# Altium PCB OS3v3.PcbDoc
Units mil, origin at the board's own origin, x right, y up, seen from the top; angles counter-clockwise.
Board outline 889.29 x 688.98 mil, 4 copper layers (Top Layer, MidLayer1, MidLayer2, Bottom Layer), stack 46.6 mil thick; 45 components, 34 nets, 157 pads, 70 vias.
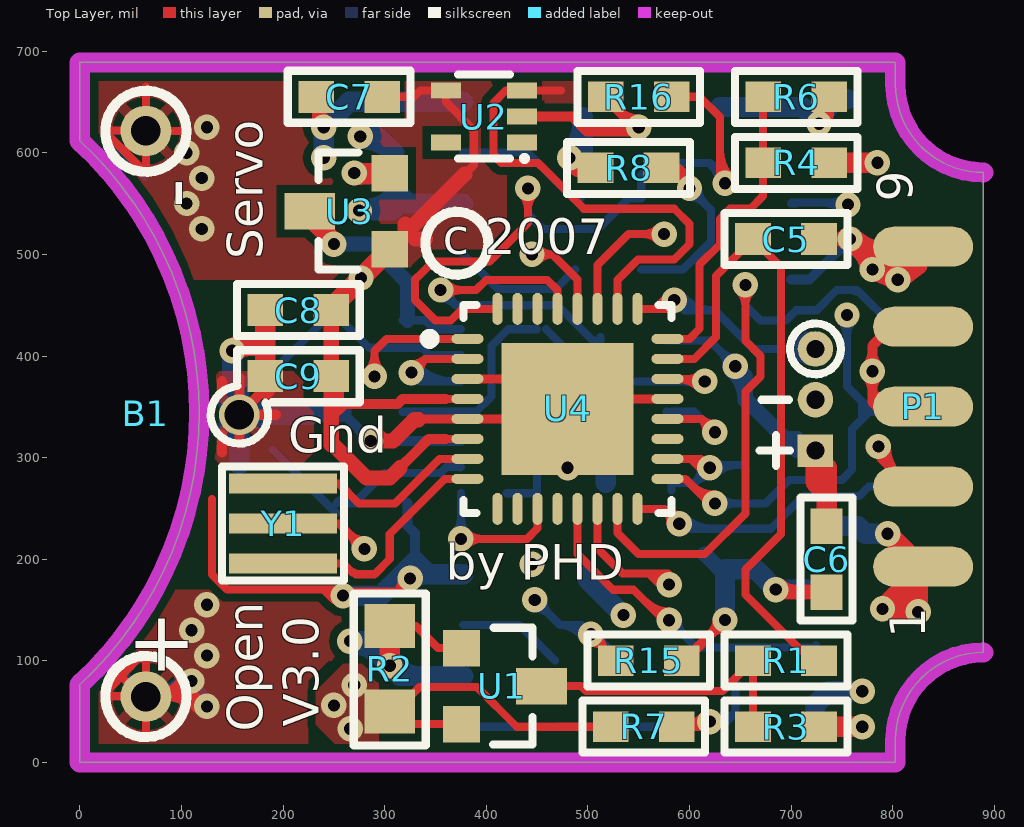
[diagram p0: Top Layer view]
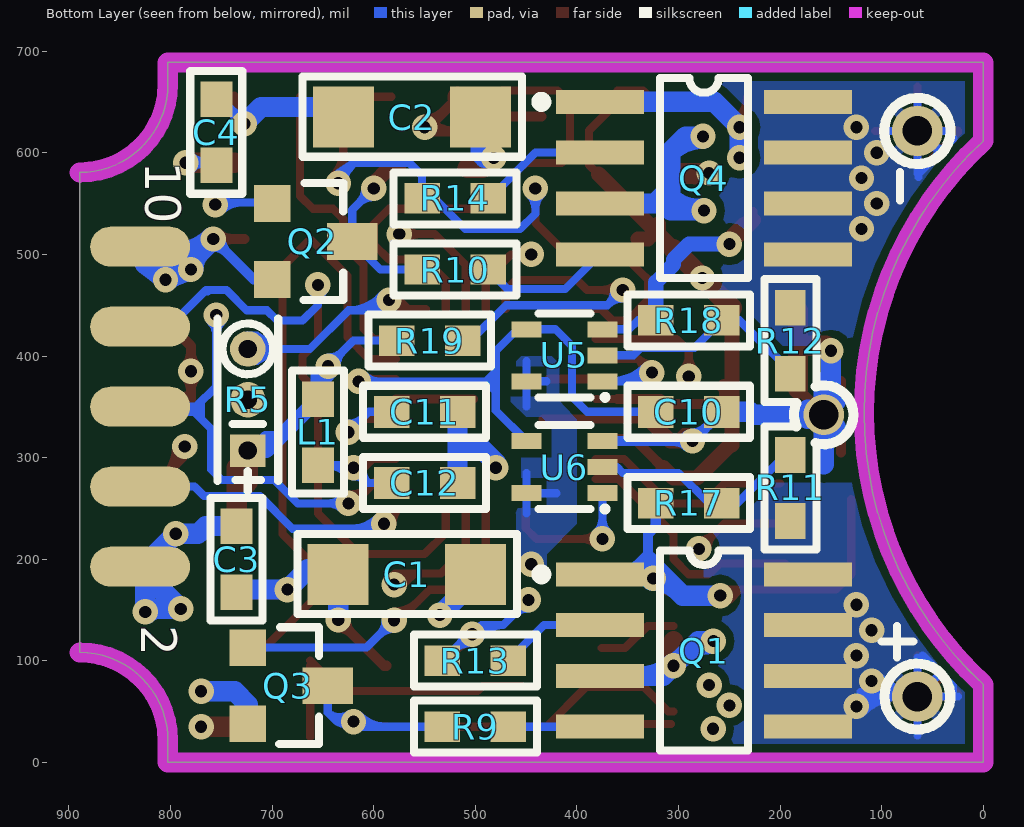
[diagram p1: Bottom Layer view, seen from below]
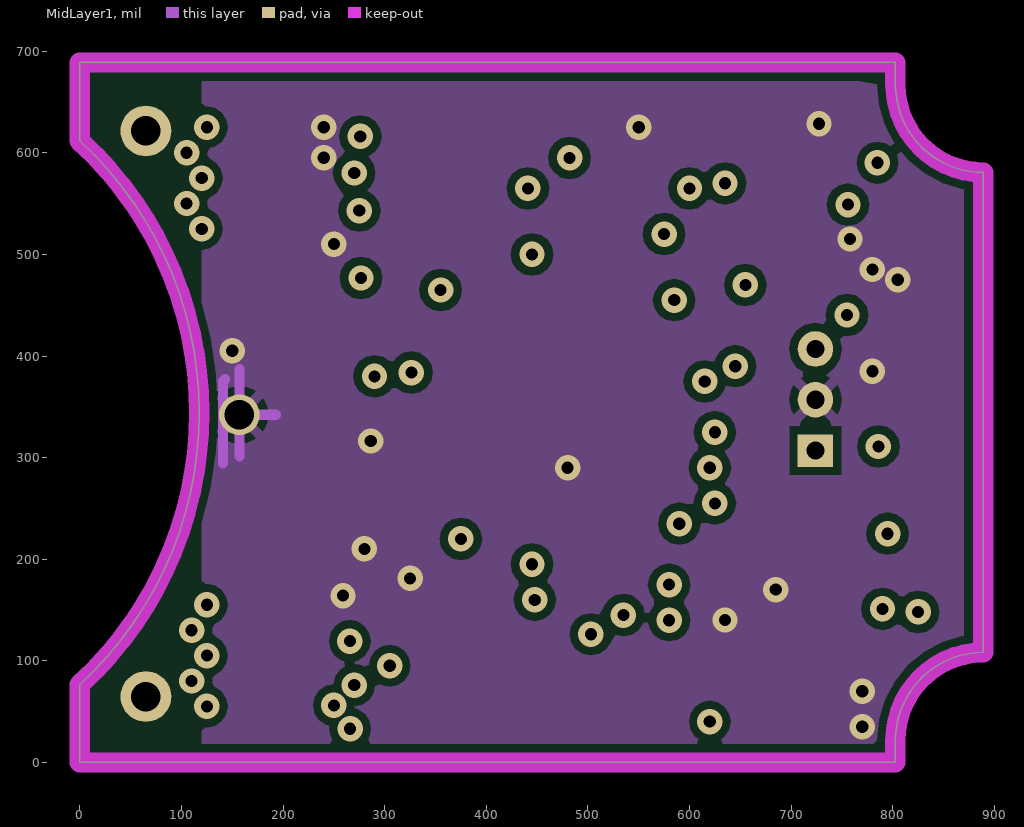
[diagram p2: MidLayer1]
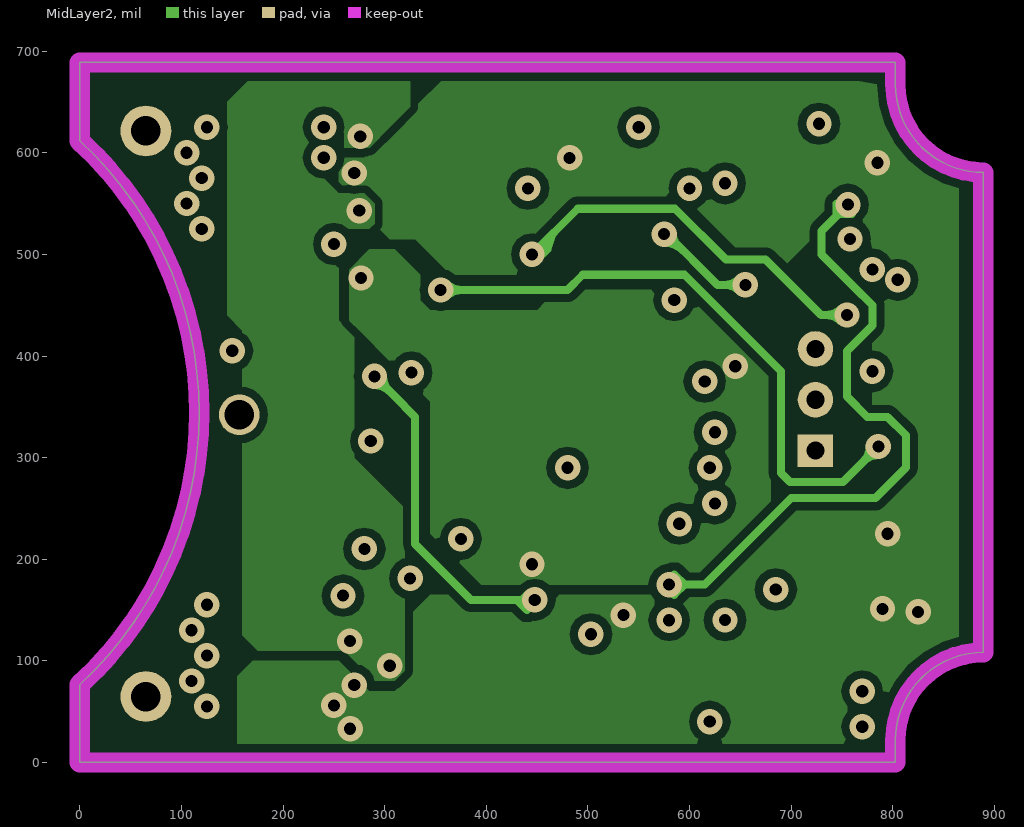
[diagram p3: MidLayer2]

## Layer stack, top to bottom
Top Layer: signal copper 1.4
Dielectric: core 5, FR-4, Dk 4.8
MidLayer1: signal copper 1.4
Dielectric: prepreg 31, FR-4, Dk 4.8
MidLayer2: signal copper 1.4
Dielectric: core 5, FR-4, Dk 4.8
Bottom Layer: signal copper 1.4

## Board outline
0,0 0,76.69 ccw(c-245.79,344.19) 117.48,344.19 ccw(c-245.79,344.19) 0,611.69 0,688.98 802.67,688.98 802.67,667.32 ccw(c889.29,667.32) 889.29,580.71 889.29,108.27 ccw(c889.29,21.65) 802.67,21.65 802.67,0

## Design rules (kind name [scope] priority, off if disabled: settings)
Clearance [All] p1: gap=8
ComponentClearance [All] p1: gap=5 collisioncheckmode=2 verticalgap=10
PasteMaskExpansion PasteMaskExpansion_1 [HasPad('U4-33')] p1: expansion=-15
PasteMaskExpansion [All] p2: expansion=0
PlaneClearance [All] p1: clearance=16
PolygonConnect PolygonConnect_2 [OnBottomLayer or OnTopLayer] p1: connectstyle=Direct reliefconductorwidth=10 reliefentries=4 polygonreliefangle="90 Angle"
PolygonConnect PolygonConnect_1 [ISVIA] p2: connectstyle=Direct reliefconductorwidth=10 reliefentries=4 polygonreliefangle="90 Angle"
PolygonConnect [All] p3: connectstyle=Relief reliefconductorwidth=10 reliefentries=4 polygonreliefangle="45 Angle"
RoomDefinition OS3v3 [InComponentClass('OS3v3')] p1: confinementstyle=ConfineIn formatcopy=TRUE lockcomponents=FALSE outline 15,0.16 1220,0.16 1220,690.16 15,690.16
RoutingVias [All] p1: holewidth=8 width=25 viastyle="Through Hole" minholewidth=8 minwidth=25 maxholewidth=28 maxwidth=50
SolderMaskExpansion SolderMaskExpansion_1 [isvia] p1: expansion=-12.99
SolderMaskExpansion [All] p2: expansion=3
TestPointUsage [All] p1 off: valid=0 allowmultiple=FALSE
Testpoint [All] p1: side=15 testpointundercomponent=TRUE minsize=40 maxsize=100 preferedsize=60 minholesize=0 maxholesize=40 preferedholesize=32 testpointgrid=1 style=1023 order=0123456789
Width [All] p1: maxlimit=100 minlimit=8 preferedwidth=10 minimp=50.000000 maximp=50.000000 favimp=50.000000
16 further rules are at their usual default settings.

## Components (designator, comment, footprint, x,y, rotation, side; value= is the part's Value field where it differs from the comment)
B1 "Motor Servo" "SERVO PADS" 65,345.16 r90 top
C1 "10uF" C1206 500,185 r0 bottom
C2 "10uF" C1206 495,635.16 r0 bottom
C3 "1uF" C0603 735,200 r270 bottom
C4 "0.1uF" C0603 755,620.16 r90 bottom
C5 "0.1uF" C0603 695,515.16 r0 top
C6 "0.1uF" C0603 735,200.16 r270 top
C7 "0.1uF" C0603 265,655.16 r180 top
C8 "0.1uF" C0603 215,445.16 r180 top
C9 "0.1uF" C0603 215,380.16 r180 top
C10 "0.001uF" C0603 290,345.16 r0 bottom
C11 "0.1uF" C0603 550,345.16 r180 bottom
C12 "0.1uF" C0603 550,275.16 r180 bottom
L1 "INDUCTOR" C0603 655,325.16 r90 bottom
P1 "Header 5X2" FD11-10E 830,350.16 r0 top
Q1 "IRF7307" SO8 275,110.16 r270 bottom
Q2 "2N7002" SOT23-3 700,550.16 r270 bottom
Q3 "2N7002" SOT23-3 724,113 r270 bottom
Q4 "IRF7307" SO8 275,575.16 r270 bottom
R1 "1K" R0603 695,100.16 r180 top
R2 "0.05" R0805 305,50.16 r90 top
R3 "4.99K" R0603 695,35.16 r0 top
R4 "10.0K" R0603 705,590.16 r180 top
R5 "RPot" "Pot Pads" 724,357 r90 bottom
R6 "20.0K" R0603 705,655.16 r0 top
R7 "2K" R0603 555,35.16 r0 top
R8 "2K" R0603 540,585.16 r0 top
R9 "10" R0603 500,35.16 r0 bottom
R10 "10" R0603 520,485.16 r0 bottom
R11 "10.0K" R0603 190,270.16 r90 bottom
R12 "10.0K" R0603 190,415.16 r270 bottom
R13 "10" R0603 500,100.16 r0 bottom
R14 "10" R0603 520,555.16 r180 bottom
R15 "100K" R0603 560,100.16 r0 top
R16 "100K" R0603 550,655.16 r180 top
R17 "20.0K" R0603 290,255.16 r0 bottom
R18 "20.0K" R0603 290,435.16 r0 bottom
R19 "10K" R0603 545,415.16 r180 bottom
U1 "ZXCT1009" SOT23-3F 415,75.16 r270 top
U2 "MCP9701A" "SC70 -5" 435,610.16 r90 top
U3 "LM3480IM3-5.0" SOT23-3 305,505.16 r90 top
U4 "ATmega168" 32M1-A_N 480,348 r0 top
U5 "SN74CBT1G125" "SC70 -5" 375,375.16 r90 bottom
U6 "SN74CBT1G125" "SC70 -5" 375,265.16 r90 bottom
Y1 "20  MHz" MXC7T 200,235.16 r270 top

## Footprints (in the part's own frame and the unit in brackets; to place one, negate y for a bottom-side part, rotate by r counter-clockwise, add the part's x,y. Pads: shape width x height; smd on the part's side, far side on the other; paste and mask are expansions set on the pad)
32M1-A_N [mm] "QFN, 32-Leads, Body 5x5mm, Pitch 0.5mm, IPC Medium Density"
  oval 0.8x0.25 smd: 1(-2.5,1.75) 2(-2.5,1.25) 3(-2.5,0.75) 4(-2.5,0.25) 5(-2.5,-0.25) 6(-2.5,-0.75) 7(-2.5,-1.25) 8(-2.5,-1.75) 17(2.5,-1.75) 18(2.5,-1.25) 19(2.5,-0.75) 20(2.5,-0.25) 21(2.5,0.25) 22(2.5,0.75) 23(2.5,1.25) 24(2.5,1.75)
  oval 0.25x0.8 smd: 9(-1.75,-2.5) 10(-1.25,-2.5) 11(-0.75,-2.5) 12(-0.25,-2.5) 13(0.25,-2.5) 14(0.75,-2.5) 15(1.25,-2.5) 16(1.75,-2.5) 25(1.75,2.5) 26(1.25,2.5) 27(0.75,2.5) 28(0.25,2.5) 29(-0.25,2.5) 30(-0.75,2.5) 31(-1.25,2.5) 32(-1.75,2.5)
  rect 3.3x3.3 smd: 33(0,0)
  silkscreen extent -3.57,-2.6 2.6,2.6, body extent -2.58,-2.58 2.58,2.58, height 1
C0603 [mm]
  rect 0.89x0.8 smd: 1(-0.825,0) 2(0.825,0)
  silkscreen extent -1.54,-0.65 1.54,0.65
C1206 [mil]
  rect 60x60 smd: 1(0,0) 2(135,0)
  silkscreen extent -41,-40 175,39
FD11-10E [mm] "Hirose 2mm, 10 pin, TH, Edge Application"
  oval 2.5x1 smd paste-5.08: 1(0,-4) 3(0,-2) 5(0,0) 7(0,2) 9(0,4)
  oval 2.5x1 smd far side paste-5.08: 2(0,-4) 4(0,-2) 6(0,0) 8(0,2) 10(0,4)
MXC7T [mm] "TDK Ceramic Resonator"
  rect 0.5x2.7 smd: 1(-1,0) 2(0,0) 3(1,0)
  silkscreen extent -1.43,-1.53 1.43,1.53
"Pot Pads" [mil]
  rect 32x35 hole 18 paste-200: 1(-50,0)
  round 35 hole 18 paste-200: 2(0,0) 3(50,0)
  silkscreen extent -80,-30 80,30
R0603 [mm]
  rect 0.89x0.76 smd: 1(-0.825,0) 2(0.825,0)
  silkscreen extent -1.54,-0.65 1.54,0.65
R0805 [mm]
  rect 1.1x1.27 smd: 1(0,0) 2(2.14,0)
  silkscreen extent -0.85,-0.9 2.95,0.9
"SC70 -5" [mm]
  rect 0.4x0.75 smd: 1(0,0) 2(0.65,0) 3(1.3,0) 4(1.3,1.9) 5(0,1.9)
  silkscreen extent -0.41,-0.08 1.7,1.6
"SERVO PADS" [mil]
  round 50 hole 29 paste-200: 1(-280.32,0) 2(276.38,0)
  silkscreen extent -320,-40 316,40
SO8 [mm] "Small Outline; 8 Leads; Body Width 3.9 mm; Pitch 1.27 mm"
  rect 0.6x2.2 smd: 1(-1.905,-2.6) 2(-0.635,-2.6) 3(0.635,-2.6) 4(1.905,-2.6) 5(1.905,2.6) 6(0.635,2.6) 7(-0.635,2.6) 8(-1.905,2.6)
  silkscreen extent -2.5,-4.19 2.5,1.1
SOT23-3 [mil]
  rect 35.98x35.98 smd: 1(0,0)
  rect 36x36 smd: 2(74.8,0)
  rect 36x50 smd: 3(37.4,78.74)
  silkscreen extent -20,31 95,70
SOT23-3F [mm] "Zetex cw pin numbers"
  rect 0.914x1.27 smd: 1(0,1)
  rect 0.914x0.914 smd: 2(0.95,-1) 3(-0.95,-1)
  silkscreen extent -1.46,-0.21 1.46,0.78

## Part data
B1: "Servo Motor"
C1 C2 C3 C4 C5 C6 C7 C8 C9 C10 C11 C12: library part "CAP NP"
P1: "Header, 5-Pin, Dual row"
Q2 Q3: "N FET"
R1 R7 R8 R9 R10 R13 R14 R15 R16 R19: library part R
R2 R3 R4 R6 R11 R12 R17 R18: library part R, "1%"
R5: "Potentiometer"
Y1: library part CRYSTAL_0

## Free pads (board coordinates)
  round 40 hole 29 paste-200: 0(157,342.16)

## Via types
v1: diameter 25, hole 12, Top Layer to Bottom Layer, 69 vias
v2: diameter 25, hole 12, Top Layer to Bottom Layer, tented top, 1 vias

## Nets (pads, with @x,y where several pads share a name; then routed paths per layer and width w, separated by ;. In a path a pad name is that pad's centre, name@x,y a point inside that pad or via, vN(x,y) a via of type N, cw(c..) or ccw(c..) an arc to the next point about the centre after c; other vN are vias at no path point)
BATTV: R4.2 R6.1 U4.24 | length 301.6
  Top Layer w8: U4.24 600,416.9 610,426.9 610,490 630,510 630,535 640,545 660,545 672.52,557.52 R6.1
BEMFV: C10.2 U4.22 U5.4 U6.4 | length 604.3
  Top Layer w8: U4.22 602.47,377.53 ; U4.22@588.38,377.53 cw(c588.38,348.38) v1@608.99,368.99 ; 600.58,377.53 ccw(c600.58,389.42) v1@608.99,381.01 ; v1@606.57,373.92 ccw(c602.47,373.4) 602.47,377.53 ; v1@608.4,380.35 cw(c602.47,385.15) 602.47,377.53 ; v1(615,375) 605,375 602.47,377.53
  Bottom Layer w8: C10.2@317.48,345.16 390.16,345.16 405,360 405,410 421.34,426.34 U5.4 ; U6.4 480,346.54 480,405 U5.4@458.66,426.34 ; 480,365.16 489.84,375 ; 480,375 489.84,375 ; 480,384.84 489.84,375 ; v1@608.99,368.99 ccw(c594.48,354.48) 594.48,375 ccw(c594.48,395.52) v1@608.99,381.01 ; v1(615,375) 489.84,375
CURRENT: C5.1 R1.1 U4.23 | length 643.5
  Top Layer w8: U4.23 604.66,397.21 626,418.55 626,478.64 C5.1 690,487.68 690,225 655,190 655,165 719.84,100.16 R1.1
EN_A: R14.1 R16.1 U4.32 | length 792
  Top Layer w8: U4.32 376.43,446.43 365,435 350,435 330,455 330,475.17 337.32,482.49 347.89,493.06 403.06,493.06 441,531 v1(441,565) ; v1@434.99,558.99 cw(c420.48,544.48) 441,544.48 cw(c461.52,544.48) v1@447.01,558.99 ; R16.1 610,655.16 630,635.16 630,583.28 ccw(c648.28,583.28) v1@635.35,570.35 ; 630,602.59 ccw(c667.59,602.59) v1@641.01,576.01
  Bottom Layer w8: v1@434.99,558.99 cw(c420.48,544.48) 441,544.48 cw(c461.52,544.48) v1@447.01,558.99 ; v1(441,565) 441,540 456,525 510,525 540,555 552.48,555 552.48,577.64 565,590.16 620,590.16 v1@635,580 ; 621.94,586.94 cw(c600,565) v1@631.01,564.37
  other v1: 635,570
EN_B: R13.2 R15.1 U4.1 | length 853.5
  Top Layer w8: v1@283.99,386.01 ccw(c269.48,400.52) 290,400.52 ccw(c310.52,400.52) v1@296.01,386.01 ; v1(290,380) 290,405 301.9,416.9 U4.1 ; v1@503,117.66 cw(c503,97.14) 517.51,111.65 cw(c532.02,126.16) v1@511.5,126.16 ; v1(503,126.16) 522.52,106.64 R15.1@522.52,95.16
  MidLayer2 w8: v1@290,371.5 cw(c290,350.98) 304.51,365.49 cw(c319.02,380) v1@298.5,380 ; v1(290,380) 309.03,360.97 330,340 330,215 385,160 v1(447.75,160) ; 410,160 435,160 v1@440,165 ; 430,160 440,150
  Bottom Layer w8: v1@447.75,151.5 cw(c447.75,130.98) 462.26,145.49 cw(c476.77,160) v1@456.25,160 ; v1(447.75,160) 472.59,135.16 ; 486.49,135.16 cw(c486.49,116.56) v1@502.57,125.91 ; v1@495.65,121.89 ccw(c472.59,108.49) 472.59,135.16 ; v1@503,117.66 cw(c503,88.73) R13.2@523.45,109.19 ; v1@503,125.16 507.48,125.16 R13.2@537.48,95.16 ; v1(503,126.16) 494,135.16 472.59,135.16 ; v1@511.5,126.16 ccw(c523.62,126.16) 515.05,117.59
GND: C1.2 C2.2 C3.2 C4.2 C5.2 C6.2 C7.2 C8.2 C9.2 C10.1 C11.2 C12.2 P1.5 P1.7 P1.9 P1.10 pad.0 Q1.1 Q2.2 Q3.2 Q4.1 R3.2 R5.2 R6.2 R15.2 R16.2 R17.2 R18.2 U2.2 U3.3 U4.3 U4.5 U4.21 U4.33 U5.3 U6.3 Y1.2 | length 4764.5
  Top Layer w8: 130,259.12 130,185.16 145,170.16 253,170.16 v1(259,164.16) ; Y1.2 255,235.16 v1(280,210.16) ; 225,170.16 239.84,170.16 v1@250,160 ; U3.3@226.26,533.9 U3.3 ; C7.2@232.52,640.14 ccw(c250.07,640.14) v1@240.28,625.57 ; v1(240,625.16) 232.52,632.64 C7.2 ccw(c260.17,655.16) v1@244.74,632.21 ; v1@271.5,210.16 ccw(c250.98,210.16) 265.49,224.67 ccw(c280,239.18) v1@280,218.66 ; 275,168.16 271,164.16 v1(259,164.16) ; v1@290,325 295,325 303.66,316.34 308.18,316.34 ; v1@316.53,180.47 cw(c300.95,179.21) 312,168.16 ; v1@324.31,172.68 ccw(c323.05,157.11) 312,168.16 ; v1(325,181.16) 312,168.16 ; v1(685,170.16) v1@687.48,167.68 ; v1(259,164.16) 263,168.16 312,168.16
  Top Layer w9: 333.35,338.16 U4.5 U4.33@433.16,338.16 ; U4.3 U4.33@427.47,377.53 ; U4.33@502.16,357.84 U4.21
  Top Layer w10: 140,305.16 140,322.52 ; 140,364.82 140,375.16 ; 157,313.92 157,378.16 ; C9.2@182.52,367.68 pad.0 193,342.16 ; U2.2 484.41,635.75 499,621.16 550.46,621.16 R16.2@517.52,654.1 ; 522.24,621.16 ccw(c522.24,652.92) v1@544.7,630.46 ; R16.2@531.16,640.46 ccw(c550,659.31) v1@550,632.66 ; R15.2@587.48,95.16 590,95.16 v1(635,140.16) ; v1@627.5,140.16 cw(c609.39,140.16) 622.2,127.35 cw(c635,114.55) v1@635,132.66 ; v1@724.39,635.47 ccw(c716.93,651.97) 733.87,645.58 ccw(c750.81,639.19) v1@734.31,631.73 ; v1@724.53,635.53 ccw(c716.14,655.16) R6.2 ; C5.2 v1(758,515.16) ; v1@728.46,626.34 ccw(c722.62,640) 737.48,640 ; v1@752.7,509.85 ccw(c739.89,497.05) 739.89,515.16 ccw(c739.89,533.26) v1@752.7,520.46 ; v1@774.7,379.7 cw(c761.89,366.89) 780,366.89 cw(c798.11,366.89) v1@785.3,379.7 ; v1@774.7,390.3 ccw(c761.89,403.11) 780,403.11 ccw(c798.11,403.11) v1@785.3,390.3 ; P1.5@785,360.16 P1.5@795,350.16 ; P1.5 784.84,350.16 780,355 780,410 798.9,428.9 P1.7 ; R6.2 737.48,638.64 v1(727.48,628.64) R6.2
  Top Layer w15: U3.3@226.26,533.9 v1(250,510.16) 250,515 U3.3@235,530 ; v1(286.34,316.34) 308.18,316.34 329.18,337.34 333.35,337.34 ; v1@687.48,167.68 C6.2 ; v1@688.54,173.69 ccw(c703.06,188.22) 703.06,167.68
  Top Layer w20: v1(150,405.16) 155,410.16 182.52,410.16 ; v1@151.77,403.39 cw(c168.11,387.05) 168.11,410.16 ; C9.2@182.52,367.68 C8.2 ; R16.2@517.52,654.1 R16.2 ; R3.2 v1(770,35.16) ; v1(758,515.16) 770.52,502.64 P1.9@825,502.64 ; v1@759.77,516.93 ccw(c794.26,551.42) P1.9@794.26,502.64 ; v1@781.85,483.48 cw(c825,444.48) P1.9@825,502.64 ; P1.5@795,350.16 P1.5 ; v1@802.99,473.52 ccw(c780,456.64) v1(780,485.16) ; v1@810,485.16 v1(780,485.16) ; P1.5@820,350.16 P1.5@825,345.16 ; P1.7@823.74,423.9 P1.7@825,423.9 ; v1(780,485.16) v1(805,475) 825,490.16 P1.9@825,502.64 ; 770.08,503.08 cw(c752.15,485.16) 777.5,485.16 ccw(c752.15,485.16) 770.08,503.08
  MidLayer1 w10: 141,294.16 141,375.16 143,377.16 ; 157,301.16 157,387.16 ; pad.0@164.07,342.16 193,342.16
  Bottom Layer w8: R18.2@317.48,435.16 340,435.16 348.82,426.34 U5.3
  Bottom Layer w10: C10.1 v1(286.34,316.34) U6.3 ; v1@278.84,316.34 ccw(c260.73,316.34) 273.54,329.14 ccw(c286.34,341.95) v1@286.34,323.84 ; v1@291.64,311.04 cw(c304.45,298.23) 304.45,316.34 cw(c304.45,334.45) v1@291.64,321.64 ; R17.2 322.48,232.68 330,225.16 330,198.16 ; Q2.2 718.2,475.35 v1(758,515.16) ; v1(727.48,628.64) C4.2@751.48,652.64 ; v1@727.48,636.14 ccw(c727.48,654.25) 740.28,641.44 ccw(c753.09,628.64) v1@734.98,628.64 ; v1@750.5,515.16 cw(c732.39,515.16) 745.2,502.35 cw(c758,489.55) v1@758,507.66
  Bottom Layer w15: v1(250,510.16) 289.84,510.16 305,495 305,490 322.48,472.52 R18.2 ; C1.2@615,205 C1.2
  Bottom Layer w20: pad.0@145.25,329.91 157,318.16 157,310.16 ; v1(150,405.16) 150,380.16 ; 157,293.16 pad.0 ; pad.0@173,338.16 177,342.16 ; pad.0@173,347.16 178,342.16 ; v1(240,595.16) v1(240,625.16) 265,650.16 Q4.1 ; C10.1 230,345.16 227,342.16 pad.0 ; v1(259,164.16) 296,164.16 330,198.16 ; 300.25,168.4 cw(c325,143.65) v1@325,178.66 ; v1@317,185.16 Q1.1 ; v1@326.77,179.39 cw(c340.69,165.46) Q1.1@340.69,185.16 ; v1@327.26,182.23 cw(c339.9,188.25) 330,198.16 ; Q1.1@343,185.16 330,198.16 ; v1(480,290) 480,295 495,310 517.52,310 ; C11.2@514,345.16 C11.2 C12.2 ; C2.2@630,645.16 710.96,645.16 v1@725.42,630.7 ; v1(635,140.16) 635,190.16 665,190.16 v1(685,170.16) 737.52,170.16 C3.2@740,167.68 ; Q3.2 724,57 737,70 v1(770,70) ; C4.2@751.48,652.64 C4.2 ; v1(758,515.16) 770.52,502.64 P1.10@825,502.64 ; v1@759.77,516.93 ccw(c794.26,551.42) P1.10@794.26,502.64 ; v1@781.85,483.48 cw(c825,444.48) P1.10@825,502.64 ; v1@802.99,473.52 ccw(c780,456.64) v1(780,485.16) ; v1@807.5,475 cw(c825.99,475) P1.10@812.91,488.07 ; P1.10@815,490.16 810,485.16 v1(780,485.16) ; 150,380.16 150,360.16 145.35,355.5 157,367.16 157,373.16 ; 150,380.16 157,373.16 ; pad.0 157,373.16 ; v1(780,485.16) v1(805,475) 825,490.16 P1.10@825,502.64 ; 770.08,503.08 cw(c752.15,485.16) 777.5,485.16 ccw(c752.15,485.16) 770.08,503.08
  other v1: 780,385 550,625.16
INTN: P1.4 U4.16 | length 382.5
  Top Layer w8: U4.16 575.43,249.57 v1(590,235) ; v1@581.5,235 ccw(c560.98,235) 575.49,249.51 ccw(c590,264.02) v1@590,243.5
  Bottom Layer w8: v1(590,235) 595,230 680,230 712.16,262.16 767.16,262.16 776.42,271.42 P1.4 ; v1@590.35,235.35 ccw(c603.28,248.28) 603.28,230 ; v1@596.01,241.01 ccw(c622.59,267.59) 622.59,230
NetB1_1: B1.1 Q1.5 Q1.6 Q1.7 Q1.8 R11.1 | length 876.4
  Top Layer w8: 41.31,85.46 41.31,83.85 B1.1@65,60.16 ; 55,100.16 25,67.96 25,65.16 B1.1@65,65.16 ; 65,26.51 65,105.16 ; B1.1@80.12,64.84 ccw(c80.12,100.48) v1@109.59,80.44 ; B1.1@81.1,64.84 cw(c81.1,11.25) v1@118.99,49.15 ; 95.23,64.84 ccw(c95.23,90.2) v1@116.2,75.94 ; 100.41,64.84 cw(c100.41,30.57) v1@124.65,54.8 ; v1@102.97,84.94 cw(c65,110.76) B1.1 115,64.84
  Bottom Layer w8: 25,64.84 115,64.84 ; 30.15,70 30.15,75.31 60,105.16 ; 42.49,87.35 B1.1 ; B1.1@52.51,64.84 ccw(c52.51,137.65) v1@103.99,86.17 ; 65,26.51 65,103.17 ; B1.1@71.82,64.84 ccw(c71.82,118.34) v1@109.65,80.51 ; B1.1@81.1,64.84 cw(c81.1,11.25) v1@118.99,49.15 ; 91.13,64.84 ccw(c91.13,99.02) v1@115.3,74.85 ; 100.41,64.84 cw(c100.41,30.57) v1@124.65,54.8 ; 110.45,64.84 ccw(c110.45,79.71) 120.96,69.2
  other v1: 125,55.16 110,80.16 125,105.16 110,130.16 125,155.16
NetB1_2: B1.2 Q4.5 Q4.6 Q4.7 Q4.8 R12.1 | length 446.3
  Top Layer w8: 25,622.16 65,622.16 44.17,601.33 ; 25.21,619.95 64.16,581 ; 65,581.84 B1.2 ; 65,665.16 B1.2 ; 106.38,621.54 B1.2
  Bottom Layer w8: 29.25,614.09 64.07,579.27 64,576.16 ; 31.72,621.54 98.28,621.54 ; 45,605.16 B1.2@48.62,605.16 ; 65,580.27 65,654.82
  other v1: 120,525.16 105,550.16 120,575.16 105,600.16 125,625.16
NetC11_1: C11.1 U4.20 | length 166.3
  Top Layer w8: U4.20 611.84,338.16 ; v1@616.52,325.61 ccw(c600.45,326.76) 611.84,338.16 ; v1@624.39,333.48 cw(c623.24,349.55) 611.84,338.16 ; v1(625,325) 611.84,338.16
  Bottom Layer w8: C11.1@577.48,345.16 C11.1@579.98,342.66 ; C11.1 604.84,345.16 v1(625,325) ; v1@616.5,325 ccw(c595.98,325) 610.49,339.51 ccw(c625,354.02) v1@625,333.5
NetC12_1: C12.1 L1.1 U4.18 | length 217.8
  Top Layer w8: U4.18 611.21,298.79 v1(620,290) ; 600,298.79 601.21,298.79 v1@615,285
  Bottom Layer w8: C12.1@582.48,267.52 C12.1 605.16,275.16 622.68,292.68 L1.1 ; v1@611.5,290 cw(c590.98,290) 605.49,275.49 cw(c620,260.98) v1@620,281.5 ; v1@626.01,283.99 cw(c646.98,263.02) L1.1@646.98,292.68 ; v1@626.01,296.01 ccw(c634.06,304.06) 634.06,292.68
NetQ1_2: Q1.2 R13.1 | length 104.7
  Bottom Layer w8: Q1.2 432.52,135.16 R13.1
NetQ1_3: Q1.3 Q4.3 R2.2 U1.3 | length 689.2
  Top Layer w8: R2.2 330.75,134.41 352.6,112.56 U1.3
  Top Layer w20: v1(305,95.16) R2.2@305,119.41
  Bottom Layer w20: v1@265.75,116.91 cw(c265.75,74.66) 295.62,104.54 ; v1(265.75,119.41) 280.75,119.41 315,85.16 Q1.3 ; v1@266.54,117.04 cw(c273.24,96.91) 288.25,111.91 ; v1(275,543.16) 308,543.16 ; v1@275.4,545.63 ccw(c281.41,582.75) 308,556.16 ; v1@276,613.66 cw(c276,566.58) 309.29,599.87 ; v1(276,616.16) 293,616.16 308,601.16 308,543.16 ; v1@276.74,613.77 cw(c284.06,590.22) 301.5,607.66 ; 295,543.16 308,556.16 ; v1@306.77,96.93 ccw(c335.18,125.34) Q1.3@335.18,85.16 ; 308,570 308,556.16 ; 308,580 308,565 322.84,550.16 325,550.16 ; Q4.3 315,550.16 308,543.16
NetQ1_4: Q1.4 R9.1 | length 90.2
  Bottom Layer w8: Q1.4 R9.1
NetQ2_3: Q2.3 R8.2 R10.2 | length 245.4
  Top Layer w8: R8.2 R8.2@579.84,585.16 ; R8.2@582.48,583.68 R8.2@582.48,585.16 ; R8.2@579.84,585.16 v1(600,565) 600,575 589.84,585.16 R8.2@579.84,585.16
  Bottom Layer w8: R10.2 593.66,485.16 Q2.3 621.26,543.9 v1@600,565.16 ; v1@600,556.5 cw(c600,535.6) 614.78,550.38 ; v1@608.5,565 ccw(c628.64,565) 614.4,550.76
NetQ3_3: Q3.3 R7.2 R9.2 | length 333.3
  Top Layer w8: 606.75,35.16 ccw(c606.75,53.36) v1@619.65,40.51 ; v1@613.98,46.16 cw(c587.48,72.57) R7.2 615,35.16 v1(620,40.16)
  Bottom Layer w8: R9.2 615,35.16 v1(620,40.16) 636.26,40.16 ; 587.41,35.16 ccw(c587.41,72.75) v1@613.99,46.17 ; 606.72,35.16 ccw(c606.72,53.44) v1@619.65,40.51 ; v1@620.28,40.57 ccw(c628.29,52.42) 638.41,42.3 ; v1@624.76,47.2 ccw(c633.82,60.59) 645.26,49.16 ; v1@626.98,35.31 cw(c636.26,28.86) 636.26,40.16 ; v1@626.98,45.01 ccw(c636.26,51.46) 636.26,40.16 ; Q3.3 645.26,49.16 ; Q3.3@646.26,75.6 Q3.3@646.26,77.76 ; 636.26,40.16 645.26,49.16
NetQ4_2: Q4.2 R14.2 | length 136.3
  Bottom Layer w8: Q4.2 440.84,600.16 485.84,555.16 R14.2 ; R14.2@487.52,557.64 R14.2 ; R14.2@492.52,555.16 R14.2
NetQ4_4: Q4.4 R10.1 | length 132.2
  Bottom Layer w8: Q4.4 411.52,466 468.36,466 R10.1
NetR1_2: R1.2 R3.1 U1.1 | length 292.6
  Top Layer w8: U1.1 493,75.16 498,70.16 632.52,70.16 R1.2 ; R3.1@662.52,25.16 R1.2@662.52,95.16
NetR11_2: R11.2 R17.1 U6.2 | length 225
  Bottom Layer w8: R11.2@190.04,307.64 R17.1@252.52,245.16 ; R17.1@252.52,255.16 R17.1@255.02,257.66 ; R17.1 270.16,255.16 300,285 355,285 360.75,290.75 U6.2 U6.2@374.41,290.16
NetR12_2: R12.2 R18.1 U5.2 | length 223.5
  Bottom Layer w8: R12.2@187.52,382.68 240,435.16 R18.1 284.48,408.2 336.8,408.2 344.25,400.75 U5.2
NetU4_7: U4.7 Y1.1 | length 207.8
  Top Layer w8: Y1.1 255,274.53 274.53,255 310,255 353.79,298.79 U4.7
NetU4_8: U4.8 Y1.3 | length 244.4
  Top Layer w8: Y1.3@195,195.79 259.21,195.79 268.09,186.91 269.87,186.91 271.62,185.16 290,185.16 305,200.16 305,225 359.1,279.1 U4.8
POSITION: R5.3 U4.25 | length 360.6
  Top Layer w8: U4.25 566.43,446.43 ; 570.97,450.97 cw(c580.91,441.03) v1@584.86,454.52 ; v1@576.76,446.43 566.43,446.43 ; v1(585,455) 575,455 566.43,446.43
  Bottom Layer w8: v1(585,455) 595,445 625,445 ; v1@585.38,455.32 ccw(c607.7,474.29) 607.7,445 ; v1@591.48,460.5 ccw(c625,488.99) 625,445 ; R5.3 663,407 625,445 ; R5.3@724,410.16 R5.3@730,410.16 ; R5.3@725,395 715,395 695,407 715,420 R5.3@725,420
PWM_A: Q3.1 U4.13 | length 375.7
  Top Layer w8: U4.13 489.84,205 524.84,170 545,170 575,140 v1(580,140) ; 556.95,158.05 ccw(c580,181.09) v1@580,148.5
  Bottom Layer w8: v1@580,131.5 cw(c580,110.98) 594.51,125.49 cw(c609.02,140) v1@588.5,140 ; v1(580,140) 607,113 Q3.1 ; Q3.1@724,115.16 Q3.1@725,115.16
PWM_B: Q2.1 U4.14 | length 966.8
  Top Layer w8: U4.14 509.53,210.47 534,186 569,186 ; 560,186 569,177 571,175 v1(580,175) 569,186 ; v1@585,180 579,186 569,186
  MidLayer2 w8: v1(580,175) 615,175 700.16,260.16 783,260.16 813,290.16 813,322 795,340 775,340 755,360 755,405 780,430 780,450 762.04,467.96 730,500 730,523 v1(756,549) ; v1@585,165 595,175 ; v1@585,185 595,175 ; v1@745,550 745,538 740.29,533.29 747,540 v1@760,540 ; 595,175 605,175 595,175
  Bottom Layer w8: Q2.1@705,550.16 Q2.1 701,551.16 753.84,551.16 v1@754.84,550.16 ; 730.27,551.16 cw(c730.27,523.27) v1@749.99,542.99 ; 740.69,551.16 ccw(c740.69,564.31) v1@749.99,555.01
RESET: P1.3 R19.2 U4.29 | length 1164
  Top Layer w8: v1(355,465) 390,465 400,475 460,475 470.16,464.84 U4.29 ; v1@361.01,458.99 cw(c375.52,444.48) 375.52,465 cw(c375.52,485.52) v1@361.01,471.01 ; v1@786.5,311 ccw(c811.47,311) 793.81,293.34 ; v1@788,305.16 788,299.16 820.74,266.42 P1.3@825,266.42 ; v1@794.5,311 ccw(c838.78,311) P1.3@807.47,279.69
  MidLayer2 w8: v1(355,465) 480,465 495,480 595,480 690,385 690,285 698.84,276.16 751.16,276.16 v1(786,311) ; v1@361.01,458.99 cw(c375.52,444.48) 375.52,465 cw(c375.52,485.52) v1@361.01,471.01 ; v1@777.5,311 cw(c756.98,311) 771.49,296.49 cw(c786,281.98) v1@786,302.5 ; v1@788,305.16 v1@788,311
  Bottom Layer w8: v1@355,456.5 cw(c355,435.98) 369.51,450.49 cw(c384.02,465) v1@363.5,465 ; v1(355,465) 370,450 470,450 504.84,415.16 R19.2 R19.2@512.52,418.64
SCK: P1.6 U4.17 U4.28 | length 1118.5
  Top Layer w8: v1(445,500) 465,500 ; v1@451.12,494.1 cw(c465,480.72) 465,500 ; v1@451.12,505.9 ccw(c465,519.28) 465,500 ; U4.28 489.84,475.16 465,500 ; U4.17 595.9,279.1 620,255 v1(625,255) ; 601.95,273.05 ccw(c625,296.09) v1@625,263.5
  MidLayer2 w8: v1(445,500) 490,545 585.85,545 635.85,495 675,495 729.65,440.35 v1(755,440.35) ; v1@455,500 460,505 464.7,519.7 ; v1@748.99,434.34 ccw(c734.48,419.83) 734.48,440.35 ccw(c734.48,460.87) v1@748.99,446.36
  Bottom Layer w8: v1(625,255) 674.84,255 698,278.16 750,278.16 760,288.16 760,328.16 777,345.16 P1.6@825,345.16 ; v1@631.01,248.99 cw(c645.52,234.48) 645.52,255 cw(c645.52,275.52) v1@631.01,261.01 ; v1@748.99,434.34 cw(c734.48,419.83) 755,419.83 cw(c775.52,419.83) v1@761.01,434.34 ; v1(755,440.35) 755,370 774.84,350.16 P1.6 ; 769.34,355.66 770,355 770,340
SDA: P1.8 U4.15 U4.27 | length 1022.3
  Top Layer w8: U4.27 509.53,489.53 540,520 v1(575,520) ; U4.15 529.21,225.79 550,205 615,205 655,245 655,365 670,380 670,400 655,415 v1(655,470) ; v1@568.99,513.99 ccw(c554.48,499.48) 554.48,520 ccw(c554.48,540.52) v1@568.99,526.01 ; v1@648.99,463.99 cw(c634.48,449.48) 655,449.48 cw(c675.52,449.48) v1@661.01,463.99
  MidLayer2 w8: v1@575,511.5 cw(c575,484.64) 594,503.63 ; v1@577.63,520 627.63,470 v1(655,470) ; v1@583.5,520 ccw(c597.68,520) 587.65,509.97 ; v1@648.99,463.99 ccw(c634.48,449.48) 634.48,470 ccw(c634.48,490.52) v1@648.99,476.01
  Bottom Layer w8: v1@649.1,463.88 cw(c635.72,450) 655,450 ; v1(655,470) 655,450 ; v1@660.9,463.88 ccw(c674.28,450) 655,450 ; 763.38,463.38 765,465 ; P1.8 801.1,428.9 765,465 ; 655,450 670,435 695,435 705,445 725,445 745,465 765,465
SMPLN_A: U4.11 U6.1 | length 208.5
  Top Layer w8: v1(375,220) 440,220 450.47,230.47 U4.11 ; v1@381.01,213.99 cw(c395.52,199.48) 395.52,220 cw(c395.52,240.52) v1@381.01,226.01
  Bottom Layer w8: v1@368.99,226.01 ccw(c354.48,240.52) 375,240.52 ccw(c395.52,240.52) v1@381.01,226.01 ; v1(375,220) U6.1
SMPLN_B: U4.2 U5.1 | length 204.8
  Top Layer w8: v1(326.3,383.7) 339.82,397.21 ; v1@326.74,392.19 ccw(c327.63,409.4) 339.82,397.21 ; v1@334.79,384.13 cw(c352.01,385.02) 339.82,397.21 ; U4.2 339.82,397.21
  Bottom Layer w8: v1(326.3,383.7) 334.84,375.16 U5.1 ; v1@326.66,384.05 ccw(c348.13,405.52) 348.13,375.16 ; v1@332.31,389.71 ccw(c367.44,424.83) U5.1@367.44,375.16
TEMPV: U2.3 U4.26 | length 477.7
  Top Layer w8: 473.66,661.34 U2.3 419.18,661.34 407,649.16 407,598.28 415.13,590.16 450.84,590.16 459.14,581.86 496,545 585,545 600,530 600,510 585,495 549.21,495 529.21,475 U4.26
VBATT: C1.1 C2.1 C3.1 C4.1 P1.1 P1.2 R2.1 R4.1 R7.1 R8.1 U1.2 U3.2 | length 1146.6
  Top Layer w8: R2.1 310.16,50.16 334.16,74.16 391,74.16 430,35.16 R7.1 ; R2.1@307.6,37.76 U1.2
  Top Layer w20: v1(270,580.16) 270.2,579.96 U3.2 v1@275.32,578.51 ; v1(482,595) R8.1@495,585.16 ; v1@483.96,596.55 ccw(c507.52,615.21) R8.1 R8.1@495,585.16 ; v1@484.5,595.13 ccw(c495,595.67) R8.1@495,585.16 ; R8.1@503.26,586.82 R8.1@507,585.16 ; R4.1 v1(785,590.16) ; v1(795,225.16) 825,195.16 v1(825,148.16) ; 811.72,151.16 cw(c811.72,134.88) v1@823.23,146.39 ; v1@822,151.16 v1(790,151.16) P1.1@825,186.16
  Bottom Layer w10: C4.1@760,592.68 760,591.16 v1(785,590.16) ; v1@779.49,585.07 ccw(c766.18,572.79) 766.91,590.88 ccw(c767.63,608.97) v1@779.91,595.67
  Bottom Layer w20: v1@480.23,596.77 ccw(c444.58,632.42) C2.1@495,632.42 ; v1@491,595 v1(482,595) C2.1@495,609 ; 495,599 C2.1 ; C1.1 500,180 v1(535,145) ; C3.1@735,232.64 C3.1@737.5,230.14 ; C3.1@740,232.64 765.52,232.64 773,225.16 v1(795,225.16) 825,195.16 v1(825,148.16) 822,151.16 v1(790,151.16) P1.2@825,186.16 ; 811.72,151.16 cw(c811.72,134.88) v1@823.23,146.39
  other v1: 266,33.16 250,56.16 270,76.16
VREG: C6.1 C7.1 C8.1 C9.1 L1.2 R5.1 R19.1 U2.4 U3.1 U4.4 U4.6 U5.5 U6.5 | length 1464.2
  Top Layer w8: C7.1 328.82,655.16 335,661.34 U2.4 360.2,649.96 388,622.16 388,588.16 378.82,578.98 ; 360,318.47 U4.6 ; 360,357.84 U4.4
  Top Layer w10: 247.48,340 260.12,352.64 275,352.64 ; C9.1@247.48,365 259.84,352.64 ; 250.12,352.64 312.64,352.64 317.84,357.84 360,357.84 ; C9.1@255,370 255,357.48 259.84,352.64 ; 265,352.64 259.84,352.64 ; 267.04,295 272.04,290 ; 270,352.64 259.84,352.64 ; 315,290 330.09,305.09 343.47,318.47 360,318.47
  Top Layer w15: C8.1 247.48,312.52 249.52,312.52 282.04,280 305,280 315,290 ; 250.12,352.64 250.12,365.12 C9.1@255,370 ; U3.1 378.82,578.98 ; U3.1@320,520 320,530 ; 330,515.16 340,515.16
  Top Layer w20: C8.1@247.48,447.64 U3.1 ; R5.1 724,276 ; R5.1@730,307 R5.1@730,310.16 ; C6.1 735,265 ; 735,290 735,265 ; 724,276 735,265 ; 724,276 735,265
  Bottom Layer w8: 420,265 U6.5@449.8,265 ; 430.16,375.16 U5.5 ; 449.8,245.2 449.8,284.8 ; 449.8,350.2 449.8,394.8 ; R19.1 619.84,415.16 v1(645,390) ; v1@636.5,390 ccw(c615.98,390) 630.49,404.51 ccw(c645,419.02) v1@645,398.5
  Bottom Layer w15: v1@641.64,386.3 cw(c614.26,356.13) L1.2@655,356.13 ; v1(645,390) 655,380 L1.2 705.64,307 R5.1 ; 693.71,318.93 706.07,318.93 ; 697.86,314.78 705,307.64
  Bottom Layer w20: R5.1@725,310.16 R5.1@730,310.16
  other v1: 276.66,476.82
  other v2: 445,195
pads on no net: U2.1 U2.5 U4.9 U4.10 U4.12 U4.19 U4.30 U4.31

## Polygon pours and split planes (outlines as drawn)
GND on Top Layer "Top Layer-GND 1" (solid, remove dead copper, pour order 1000): 125,385.16 210,385.16 220,375.16 220,355.16 230,345 230,305 220,295 125,295.16
TEMPV on Top Layer "Top Layer-TEMPV" (solid, pour order 1000): 455,680.16 455,630.75 495,630.75 495,680.16
NetB1_2 on Top Layer "Bottom Layer-NetB1_2" (solid, remove dead copper, pour order 1001): -1,695.16 230,695.16 255,670.16 255,480.16 250,475.16 100,475.16 89,497.16 -1,623.16 -2,697.16
NetB1_1 on Top Layer "Top Layer-NetB1_1" (solid, remove dead copper, pour order 1000): 75,170.16 250,170.16 270,150.16 270,100.16 245,100.16 225,80.16 225,-9.84 -7,-8.84 -7,68.16
VBATT on Top Layer "Top Layer-VBATT" (solid, pour order 1000): 294,16.16 253,16.16 232,37.16 232,70.16 259,97.16 278,97.16 294,81.16
VREG on Top Layer "Top Layer-VREG" (solid, remove dead copper, pour order 1001): 320,475 420,475.16 420,680.16 320,680.16 320,630.16 290,630.16 290,530.16 320,530
GND on MidLayer1 "MidLayer1-GND" (solid, remove dead copper, pour order 1001): 120,700.16 800,700.16 800,665.16 870,575 870,110 805,20.16 805,-9.84 120,-4.84
VREG on MidLayer2 "MidLayer2-VREG" (solid, pour order 1003): 285,505.16 310,505 335,480 335,455 345,445 450,445 470,465 600,465 680,385 680,250 605,175 395,175 345,225 345,355 265,435 265,485.16
NetQ1_3 on MidLayer2 "MidLayer2-NetQ1_3" (solid, remove dead copper, pour order 1000): 305,690.16 325,670.16 325,645.16 285,605.16 260,605.16 260,620.16 240,620.16 240,575.16 255,560.16 280,560.16 290,550.16 290,530.16 285,525.16 255,525.16 255,435 270,420 270,300 320,250 320,90.16 310,80.16 290,80.16 260,110.16 175,110 160,125 160,425 145,440 145,650.16 185,690.16
VBATT on MidLayer2 "MidLayer2-VBATT" (solid, remove dead copper, pour order 1002): 380,695.16 280,595.16 260,595.16 255,590.16 255,570.16 260,565.16 280,565.16 295,550.16 295,525.16 305,515.16 330,515 365,480 685,480.16 720,515.16 745,515.16 780,475 780,250.16 670,250.16 585,165 345,165 325,145 325,85 310,70.16 285,70.16 255,100.16 170,100 155,85 155,-10 795,-9.84 795,35.16 865,110 865,580 800,660.16 800,695.16
NetB1_2 on Bottom Layer "Bottom Layer-NetB1_2" (solid, remove dead copper, pour order 1001): -1,695.16 230,695.16 275,650.16 275,435.16 250,410.16 115,410.16 89,497.16 -1,623.16 -2,697.16
NetB1_1 on Bottom Layer "Bottom Layer-NetB1_1" (solid, remove dead copper, pour order 1004): 112,275.16 265,275.16 275,265.16 275,45.16 250,45.16 250,-9.84 -7,-8.84 -7,68.16
VREG on Bottom Layer "Bottom Layer-VREG" (solid, remove dead copper, pour order 1000): 460,190 460,245 465,250 430,250 430,280 455,280 455,300 425,300 425,330 435,340 450,340 465,355 465,360 430,360 430,390 460,390 460,395 455,400 425,400 415,390 415,355 400,340 400,235 430,205 430,190

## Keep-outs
MidLayer1:
  lines w20: 889.29,108.27 889.29,580.71
MidLayer2:
  lines w20: 889.29,108.27 889.29,580.71
Keep-Out Layer:
  lines w20: 889.29,108.27 ccw(c889.29,21.65) 802.67,21.65 802.67,0 0,0 0,76.69 ccw(c-245.79,344.19) 117.48,344.19 ccw(c-245.79,344.19) 0,611.69 0,688.98 802.67,688.98 802.67,667.32 ccw(c889.29,667.32) 889.29,580.71

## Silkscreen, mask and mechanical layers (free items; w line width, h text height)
Top Overlay:
  circle w8: c724,407 r25
  lines w7.99: 154.57,374.16 154.57,405.75 ; 189,354.57 275.43,354.57 ; 669,307 699,307 ; 671,357 698,357 ; 685,292 685,322
  lines w8: 154.85,370.38 ccw(c157,342.16) 182.7,354.02
  lines w10: 402,513 ccw(c371.05,511) 402.05,511.94
  text "c 2007" at 357,500 h35
  text "Servo" at 180,495.16 h35 r90
  text "Gnd" at 205,305 h35
  text "by PHD" at 360,180 h35
  text "V3.0" at 235,35 h35 r90
  text "Open" at 180,30.16 h35 r90
Bottom Overlay:
  circle w10: c65,64.84 r32.45
  circle w10: c65,621.54 r32.62
  circle w8: c724,407 r25
  lines w7.99: 69,119.16 100,119.16 ; 82,553.16 82,581.16 ; 85,103.16 85,134.16 ; 164.41,209.72 164.41,313.5 ; 164.41,370.61 164.41,475.59 ; 184.53,330.59 215.59,330.59 ; 184.87,354.72 215.59,354.72 ; 709,333 739,333 ; 711,278.16 736,278.16 ; 724,267 724,287
  lines w10: 164.95,370.06 ccw(c157,342.16) 165.25,314.34 ; 184,353.86 cw(c157,342.16) 184.2,330.92
Mechanical 5:
  lines w7.99: 60,125 60,310 ; 60,385 60,560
